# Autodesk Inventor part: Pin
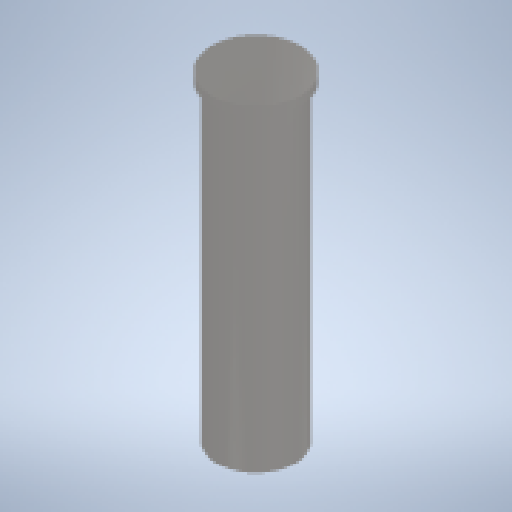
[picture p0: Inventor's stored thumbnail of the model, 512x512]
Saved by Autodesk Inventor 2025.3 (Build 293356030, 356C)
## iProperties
Created: 2025-10
Part Number: Pin
Material: Acero inoxidable
Document SubType Name: Modeling
Designer: Asus
Density: 8 g/cm^3
Appearance: Semipulido
Author: Asus
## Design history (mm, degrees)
sketch "Boceto1"
  geometry: C1 r 25.4 at (0, 0); 1 further point
  constraints: 1 centre point, 1 coincident
  dimensions: "d0" = 50.8 diameter of C1
extrude "Extrusión1" new body sketch "Boceto1" distance "d1" = 5; taper "d2" = 0 deg
sketch "Boceto2"
  geometry: C1 r 22.5 at (0, 0); 1 further point
  constraints: 1 centre point, 1 coincident
  dimensions: "d3" = 45 diameter of C1
extrude "Extrusión2" join sketch "Boceto2" distance "d4" = 180; taper "d5" = 0 deg
sketch "Boceto3"
  geometry: 2 further points
  constraints: 1 coincident
hole "Agujero1" sketch "Boceto3" at (0, 0) diameter "d6" = 16.3068; stored, may be unused: countersink angle "d10" = 90 deg, drill point angle "d12" = 118 deg; dims "d7" = 38.1, "d8" = 4, "d9" = 2, "d11" = 20
node "Sólido1"
